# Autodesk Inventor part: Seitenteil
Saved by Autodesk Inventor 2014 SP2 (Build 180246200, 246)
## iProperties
Created: 2015-07
Part Number: Seitenteil
Material: Generisch
Document SubType Name: Modeling
Designer: e_krauts
Density: 1 g/cm^3
Appearance: Vorgabe
Mass: 43.9176 g
Surface Area: 202.872 cm^2
Volume: 43.9176 cm^3
Sending System: SolidWorks 2011
Last Author: e_boekem
Sachnummer: NWS 100-00-01
Erstellt durch: XYZ
Werkstoff: AlCu4PbMg
Einheit: Stck.
Author: e_krauts
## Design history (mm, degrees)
node "Seitenteil.ipt1"
node "M5 Gewindebohrung1"
node "Basis1"
